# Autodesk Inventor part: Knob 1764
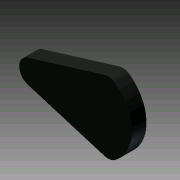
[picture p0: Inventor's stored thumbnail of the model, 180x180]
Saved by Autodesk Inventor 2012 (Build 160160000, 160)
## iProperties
Created: 2010-02
Part Number: Knob 1764
Document SubType Name: Modeling
Designer: jgehrig
Density: 1 g/cm^3
Material: Default
Author: jgehrig
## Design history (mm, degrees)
sketch "Sketch1"
  geometry: C1 r 4.445 at (0, 0); 1 further point
  constraints: 1 centre point, 1 coincident
  dimensions: "d0" = 8.89 diameter of C1
extrude "Extrusion1" new body sketch "Sketch1" distance "d1" = 1.27; taper "d2" = 0 deg
sketch "Sketch2"
  geometry: C1 r 4.445 at (0, 0) reference; C2 r 1.27 at (0, 0)
  constraints: 1 centre point, 1 coincident
  dimensions: "d3" = 2.54 diameter of C2
extrude "Extrusion2" join sketch "Sketch2" distance "d4" = 1.27; taper "d5" = 0 deg
sketch "Sketch3"
  geometry: C1 r 4.445 at (0, 0) reference; C2 r 3.175 at (0, 0)
  constraints: 1 centre point, 1 coincident
  dimensions: "d6" = 6.35 diameter of C2
extrude "Extrusion3" join sketch "Sketch3" distance "d7" = 1.27; taper "d8" = 0 deg
sketch "Sketch4"
  geometry: L1 (6.35, -9.525)-(6.35, 9.525); L2 (4.958, 9.1)-(-14.907, 3.037); L3 (-14.907, -3.037)-(4.958, -9.1); C1 r 3.175 at (0, 0) reference; A1 r 10.795 centre (1.27, 0) between (7.808, -8.59) and (7.808, 8.59); A2 r 3.175 centre (-13.98, 0) between (-14.907, 3.037) and (-14.907, -3.037); A3 r 3.175 centre (5.885, 6.063) between (7.808, 8.59) and (4.958, 9.1); A4 r 3.175 centre (5.885, -6.063) between (4.958, -9.1) and (7.808, -8.59); 1 further point
  constraints: 10 point on circle, 6 end point, 6 tangent, 4 centre point, 4 point on line, 1 equal radius, 1 vertical
  dimensions: "d9" = 19.05 distance of L1.start L1.end; "d13" = 9.525 vertical distance of L1.start C1.centre; "d14" = 6.35 distance from line of L1 C1.centre; "d15" = 10.795 radius of A1; "d16" = 3.175 radius of A2; "d20" = 0 vertical distance of C1.centre A2.centre; "d21" = 22.225 distance of L1.end L2.end; "d22" = 3.175 radius of A3
extrude "Extrusion4" join sketch "Sketch4" distance "d17" = 3.81; taper "d18" = 0 deg
body "Solid1"
